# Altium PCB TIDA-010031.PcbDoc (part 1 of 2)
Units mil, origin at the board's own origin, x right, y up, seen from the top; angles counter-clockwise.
Board outline 1982.49 x 1977.57 mil, 2 copper layers (Top Layer, Bottom Layer), stack 62 mil thick; 85 components, 79 nets, 332 pads, 189 vias.
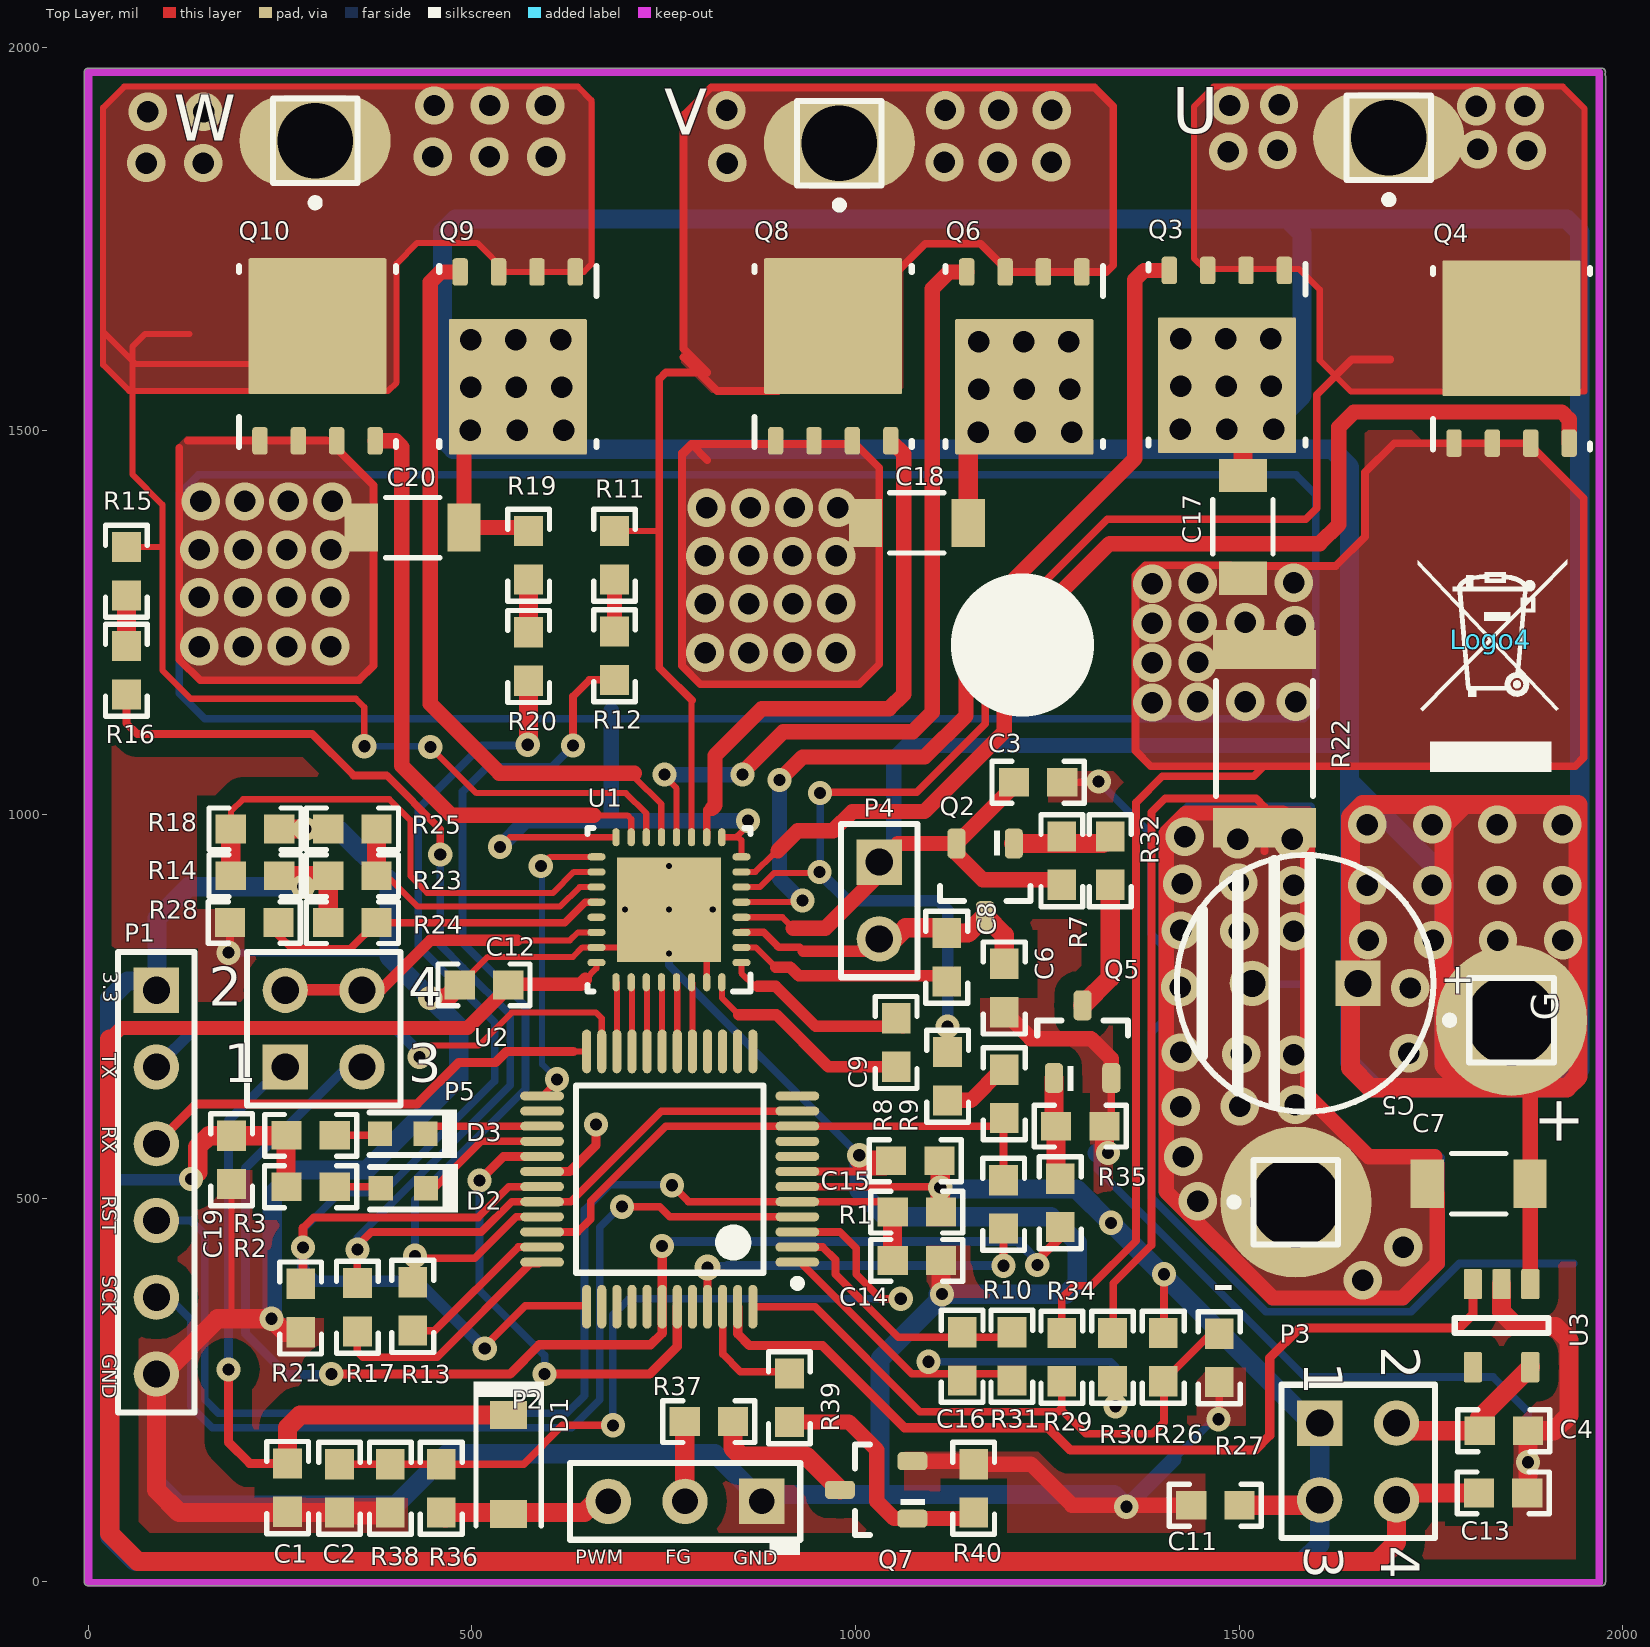
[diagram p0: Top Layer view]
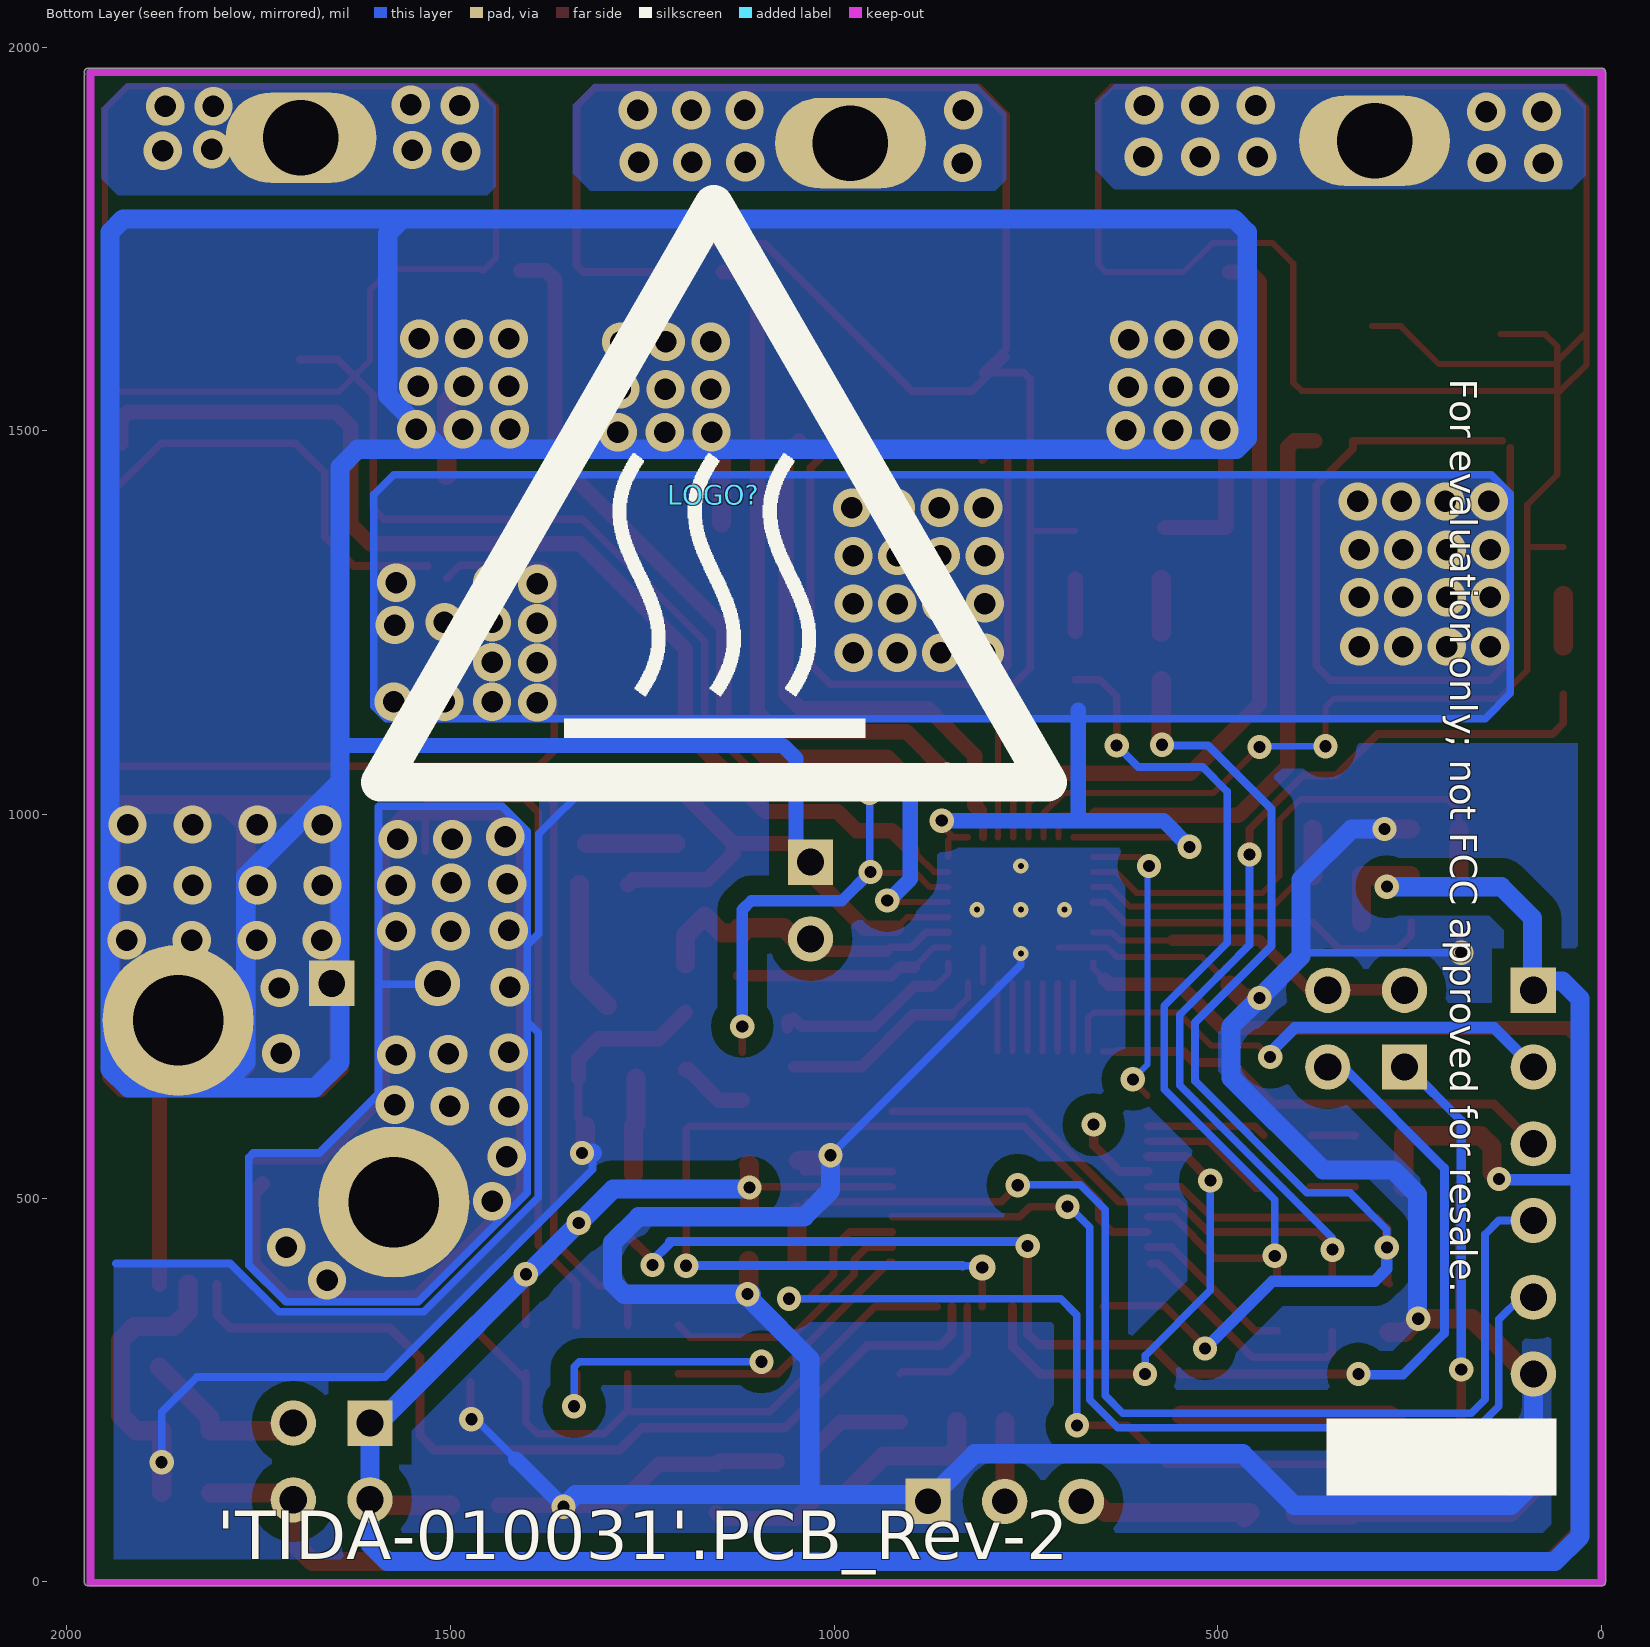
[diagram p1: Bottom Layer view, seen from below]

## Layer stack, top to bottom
Top Solder: solder mask 0.4, Solder Resist, Dk 3.5
Top Layer: signal copper 1.4
Dielectric1: core 59.2, FR-4, Dk 4.8
Bottom Layer: signal copper 1.4
Bottom Solder: solder mask 0.4, Solder Resist, Dk 3.5

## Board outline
0,-5.01 cw(c0,0) -5.01,0 -5.01,1967.54 cw(c0,1967.54) 0,1972.55 1972.46,1972.55 cw(c1972.46,1967.54) 1977.48,1967.54 cw(c1972.46,1967.54) 1976.67,1964.8 cw(c1972.46,1962.07) 1977.48,1962.07 1977.48,0 cw(c1972.46,0) 1972.46,-5.01

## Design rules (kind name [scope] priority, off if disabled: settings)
AcuteAngle [All] p1: minimum=4.50000000000000E+0001 checktracksonly=FALSE
Clearance Clearance_2 [InNet('GND')] p1 off: gap=25 ignorepadtopadclearanceinfootprint=FALSE except(0: Arc-Hole Track-Hole SMDPad-Hole THPad-Hole Via-Hole Fill-Hole Poly-Hole Region-Hole Text-Hole)
Clearance Clearance_Poly [InPolygon] p2 off: gap=10 ignorepadtopadclearanceinfootprint=FALSE except(0: Arc-Hole Track-Hole SMDPad-Hole THPad-Hole Via-Hole Fill-Hole Poly-Hole Region-Hole Text-Hole)
Clearance Clearance_FiducialMark [IsKeepOut and InComponentClass('FiducialMark') vs IsPad and InComponentClass('FiducialMark')] p3 off: gap=30 ignorepadtopadclearanceinfootprint=FALSE except(0: Arc-Hole Track-Hole SMDPad-Hole THPad-Hole Via-Hole Fill-Hole Poly-Hole Region-Hole Text-Hole)
Clearance [All] p4: gap=6 ignorepadtopadclearanceinfootprint=FALSE except(0: Arc-Hole Track-Hole SMDPad-Hole THPad-Hole Via-Hole Fill-Hole Poly-Hole Region-Hole Text-Hole)
ComponentClearance ComponentClearance_MountingHoles_FiducialMarks [InComponentClass('Mounting Holes') vs InComponentClass('FiducialMark')] p1: gap=50 collisioncheckmode=3 verticalgap=10 showdistances=FALSE
ComponentClearance ComponentClearance_Shunt [InComponentClass('Header') vs InComponentClass('Shunt')] p2 off: gap=0 collisioncheckmode=3 verticalgap=0 showdistances=FALSE
ComponentClearance ComponentClearance_Logo [InComponentClass('Logo')] p3 off: gap=50 collisioncheckmode=3 verticalgap=10 showdistances=FALSE
ComponentClearance ComponentClearance_ScrewToNut [(HasFootprint('NY PMS 440 0025 PH')) vs (HasFootprint('Keystone_1902C'))] p4 off: gap=5 collisioncheckmode=3 verticalgap=10 showdistances=FALSE
ComponentClearance ComponentClearance_MountingHoles [InComponentClass('Mounting Holes')] p5 off: gap=250 collisioncheckmode=3 verticalgap=100000 showdistances=FALSE
ComponentClearance ComponentClearance_SmallPassives [HasFootprint('0201*') or HasFootprint('0402*') or HasFootprint('0508') or HasFootprint('0603*') or HasFootprint('0612') or HasFootprint('0805*') or HasFootprint('0815*') or HasFootprint('0830*') or HasFootprint('1206*') or HasFootprint('1210*') or HasFootprint('1808*') or HasFootprint('1812*') or HasFootprint('1825*') or HasFootprint('2010*') or HasFootprint('2220*') or HasFootprint('2225*') or HasFootprint('2512*') or HasFootprint('2728*') or HasFootprint('3518*') vs HasFootprint('0201*') or HasFootprint('0402*') or HasFootprint('0508') or HasFootprint('0603*') or HasFootprint('0612') or HasFootprint('0805*') or HasFootprint('0815*') or HasFootprint('0830*') or HasFootprint('1206*') or HasFootprint('1210*') or HasFootprint('1808*') or HasFootprint('1812*') or HasFootprint('1825*') or HasFootprint('2010*') or HasFootprint('2220*') or HasFootprint('2225*') or HasFootprint('2512*') or HasFootprint('2728*') or HasFootprint('3518*')] p6 off: gap=14.96 collisioncheckmode=3 verticalgap=10 showdistances=FALSE
ComponentClearance ComponentClearance_THtoSMT [IsThruComponent vs IsSMTComponent] p7 off: gap=40 collisioncheckmode=3 verticalgap=30 showdistances=FALSE
ComponentClearance ComponentClearance_THtoTH [IsThruComponent vs IsThruComponent] p8 off: gap=30 collisioncheckmode=3 verticalgap=30 showdistances=FALSE
ComponentClearance [All] p9 off: gap=30 collisioncheckmode=3 verticalgap=10 showdistances=FALSE
DiffPairsRouting [All] p1: maxlimit=100 minlimit=10 mostfreqgap=10 toplayer_minwidth=15 toplayer_maxwidth=15 toplayer_prefwidth=15 bottomlayer_minwidth=15 bottomlayer_maxwidth=15 bottomlayer_prefwidth=15 maxuncoupledlength=1000
FabricationTestPointUsage TestPointUsage [All] p1: valid=2 allowmultiple=FALSE
FabricationTestpoint Testpoint [(IsPad And (OnTopLayer Or OnBottomLayer))] p1: side=3 testpointundercomponent=TRUE minsize=40 maxsize=100 preferedsize=60 minholesize=0 maxholesize=40 preferedholesize=32 testpointgrid=1 allowsidetop=TRUE allowsidebottom=TRUE usegrid=TRUE gridtolerance=0.01
FanoutControl Fanout_LCC [IsLCC] p1: bgadir=Out bgaviamode=Centered fanoutstyle=Auto fanoutdirection=Alternating viagrid=1 // Fanout_LCC (Default Rule)
FanoutControl Fanout_BGA [IsBGA] p2 off: bgadir=Out bgaviamode=Centered fanoutstyle=Auto fanoutdirection=Alternating viagrid=1 // Fanout_BGA (Default Rule)
FanoutControl Fanout_Default [All] p4: bgadir=Out bgaviamode=Centered fanoutstyle=Auto fanoutdirection=Alternating viagrid=1 // Fanout_Default (Default Rule)
FanoutControl Fanout_Small [(CompPinCount < 5)] p5: bgadir=Out bgaviamode=Centered fanoutstyle=Auto fanoutdirection=OutThenIn viagrid=1 // Fanout_Small (Default Rule)
HoleSize [All] p1: absolutevalues=TRUE maxlimit=251 minlimit=7.87 maxpercent=80.000 minpercent=20.000
MinimumAnnularRing MinimumAnnularRing_ThermalPadVias [IsVia and InAnyComponent] p1: minimumring=5.91
MinimumAnnularRing [All] p2 off: minimumring=8
MinimumSolderMaskSliver MinimumSolderMaskSliver_Logo [InComponentClass('Logo') vs InComponentClass('Logo')] p1: minsoldermaskwidth=0.7
MinimumSolderMaskSliver [All] p2 off: minsoldermaskwidth=3.94
PlaneConnect [All] p1: planeconnectstyle=Relief reliefexpansion=10 reliefentries=4 reliefconductorwidth=10 reliefairgap=10
PolygonConnect [All] p1: connectstyle=Direct reliefconductorwidth=10 reliefentries=4 polygonreliefangle="90 Angle" airgapwidth=10
RoutingVias ThermalPadVias [IsVia and InAnyComponent] p1: holewidth=7.87 width=19.68 viastyle="Through Hole" minholewidth=7.87 minwidth=19.68 maxholewidth=12.99 maxwidth=23.62
RoutingVias [All] p2: holewidth=16 width=34 viastyle="Through Hole" minholewidth=7.87 minwidth=26 maxholewidth=40 maxwidth=65
SilkToSilkClearance SilkToSilkClearance_Pb-FreeLogo [(HasFootprint('Pb-Free_Overlay_Medium') OR HasFootprint('Pb-Free_Overlay_Small')) vs (HasFootprint('Pb-Free_Overlay_Medium') OR HasFootprint('Pb-Free_Overlay_Small'))] p1 off: silktosilkclearance=0
SilkToSilkClearance [All] p2 off: silktosilkclearance=4
SilkToSolderMaskClearance SilkToComponentPadClearance [(IsPad or IsFill or IsRegion) and InAnycomponent] p1 off: minsilkscreentomaskgap=5 clearancetoexposedcopper=TRUE
SilkToSolderMaskClearance "Silk to Solder Mask Opening" [IsPad] p2 off: minsilkscreentomaskgap=4 clearancetoexposedcopper=TRUE
SolderMaskExpansion [All] p1: expansion=1.97
Width [All] p1: maxlimit=100 minlimit=6 preferedwidth=10 checkconnectedcopper=TRUE
17 further rules are at their usual default settings.

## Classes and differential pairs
component class TIDA-010031_Page1: + - C1 C2 C3 C4 C5 C6 C7 C8 C9 C11 C12 C13 C14 C15 C16 C17 C18 C19 C20 D1 D2 D3 P1 P2 P3 P4 P5 Q2 Q3 Q4 Q5 Q6 Q7 Q8 Q9 Q10 R1 R2 R3 R7 R8 R9 R10 R11 R12 R13 R14 R15 R16 R17 R18 R19 R20 R21 R22 R23 R24 R25 R26 R27 R28 R29 R30 R31 R32 R34 R35 R36 R37 R38 R39 R40 U U1 U2 U3 V W
component class AssemblyNote: ZZ1 ZZ2
component class Header: P2
component class Label: LBL1
component class TIDA-010031_EVM_Hardware: !PCB LBL1 Logo3 Logo4 ZZ1 ZZ2

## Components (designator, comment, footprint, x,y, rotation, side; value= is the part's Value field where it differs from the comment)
+ "Socket" PIN1#1 1855,732 r90 top (schematic designator J4)
- "Socket" PIN1#1 1574,495 r90 top (schematic designator J5)
C1 "GRM188R61H105KAALD" 0603 260,123 r270 top value=1uF
C2 "C1608X5R1H104K080AA" 0603 327.65,122 r270 top value=0.1uF
C3 "GRM188R61H105KAALD" 0603 1238,1042 r0 top value=1uF
C4 "GRM188R71A225KE15J" 0603 1845,197 r0 top value=2.2uF
C5 "50ZLJ100MT78X11.5" ZLJ_800X1150 1586,780 r180 top value=100uF
C6 "C1608X5R1H104K080AA" 0603 1194,774 r270 top value=0.1uF
C7 "C3216X7R2A474K160AA" 1206_180 1812,519 r180 top value=0.47uF
C8 "GRM188R61H105KAALD" 0603 1119,814 r270 top value=1uF
C9 "C0603X223K5RACTU" 0603 1053,703 r270 top value=0.022uF
C11 "GRM188Z71A106MA73D" 0603 1469,100 r180 top value=10uF
C12 "C1608X5R1H104K080AA" 0603 516,778 r180 top value=0.1uF
C13 "GRM188R61H105KAALD" 0603 1844,116 r0 top value=1uF
C14 "GRM188R71C102KA01D" 0603 1080,419 r0 top value=1000pF
C15 "C1608X5R1H104K080AA" 0603 1078,549 r180 top value=0.1uF
C16 "06035A220JAT2A" 0603 1139,294 r270 top value=22pF
C17 "C3216X7R2A474K160AA" 1206_180 1505,1375 r270 top value=0.47uF
C18 "C3216X7R2A474K160AA" 1206_180 1080,1380 r180 top value=0.47uF
C19 "C1608X5R1H104K080AA" 0603 187,550 r270 top value=0.1uF
C20 "C3216X7R2A474K160AA" 1206_180 423,1374 r180 top value=0.47uF
D1 "1N4148W-TP" SOD-123 548,153 r270 top value=100V
D2 "LTST-C190CKT" LED_LTST-C190_Red 411,513 r0 top value=Red
D3 "LTST-C190CKT" LED_LTST-C190_Red 410,584 r0 top value=Red
Logo3 "FCC disclaimer" FCC_disclaimer 1478,2099 r0 top
Logo4 "WEEE logo" WEEE_Minimum 1828,1228 r0 top
LOGO? "CAUTION HOT SURFACE" IEC_HotSurface_Large 1157,1417.02 r180 bottom
P1 "Header 6" HDR1X6 89,771 r270 top
P2 "800-10-003-10-001000" Mill-Max_800-10-003-10-001000 778,105 r180 top
P3 "Header 2X2" HDR2X2 1605,207 r270 top
P4 "Header 2" HDR1X2 1031,938 r270 top
P5 "Header 2X2" HDR2X2 257,671 r0 top
Q2 "MMBT5401LT1G" SOT-23 1169,915 r270 top value="150 V"
Q3 "CSD18514Q5A" DQJ0008A 1484,1599 r270 top value=40V
Q4 "CSD18514Q5A" DQJ0008A 1855,1594 r90 top value=40V
Q5 "MMBT5550LT1G" SOT-23 1296,704 r90 top value="140 V"
Q6 "CSD18514Q5A" DQJ0008A 1220,1597 r270 top value=40V
Q7 "MMBT5550LT1G" SOT-23 1027,120 r180 top value="140 V"
Q8 "CSD18514Q5A" DQJ0008A 971,1597 r90 top value=40V
Q9 "CSD18514Q5A" DQJ0008A 560,1597 r270 top value=40V
Q10 "CSD18514Q5A" DQJ0008A 299,1597 r90 top value=40V
R1 "RC0603JR-0747KL" 0603 1080,482 r0 top value=47k
R2 "RC0603JR-07470RL" 0603 290,515 r180 top value=470
R3 "RC0603JR-07470RL" 0603 290.04,582 r180 top value=470
R7 "RC0603JR-0751KL" 0603 1269,940 r90 top value=51k
R8 "RC0603FR-0782KL" 0603 1120,659 r270 top value=82.0k
R9 "RC0603FR-0782KL" 0603 1194,636 r270 top value=82.0k
R10 "CRCW060315K0FKEA" 0603 1193,492 r270 top value=15.0k
R11 "RC0603FR-0782KL" 0603 686,1338 r270 top value=82.0k
R12 "RC0603FR-0782KL" 0603 686,1207 r270 top value=82.0k
R13 "CRCW060315K0FKEA" 0603 423,359 r270 top value=15.0k
R14 "RC0603JR-070RL" 0603 217.55,920.3 r0 top value=0
R15 "RC0603FR-0782KL" 0603 50,1317 r270 top value=82.0k
R16 "RC0603FR-0782KL" 0603 50,1188 r270 top value=82.0k
R17 "CRCW060315K0FKEA" 0603 351,358 r270 top value=15.0k
R18 "CRCW060347K0FKEA" 0603 217.55,981.3 r180 top value=47.0k
R19 "CRCW06031M30FKEA" 0603 574,1338 r270 top value=1.30Meg
R20 "CRCW06031M30FKEA" 0603 574,1206 r270 top value=1.30Meg
R21 "CRCW0603150KFKEA" 0603 277,357 r270 top value=150k
R22 "ERJ-M1WTF1M0U" 2512 1533,1099 r90 top value=0.001
R23 "RC0603JR-070RL" 0603 344.55,920.3 r180 top value=0
R24 "RC0603JR-070RL" 0603 344.55,859.3 r180 top value=0
R25 "CRCW060375K0JNEA" 0603 344.55,981.3 r0 top value=75k
R26 "CRCW06037K50FKEA" 0603 1401,293 r270 top value=7.50k
R27 "CRCW06037K50FKEA" 0603 1474,292 r270 top value=7.50k
R28 "CRCW06031M00FKEA" 0603 216.55,859.3 r0 top value=1.00Meg
R29 "ERJ-3EKF1001V" 0603 1269,293 r270 top value=1.00k
R30 "ERJ-3EKF1001V" 0603 1335,293 r270 top value=1.00k
R31 "RC0603FR-0720KL" 0603 1204,294 r90 top value=20.0k
R32 "ERJ-3GEYJ104V" 0603 1332,940 r90 top value=100k
R34 "RC0603JR-0751KL" 0603 1267,494 r90 top value=51k
R35 "ERJ-3GEYJ104V" 0603 1293,594 r180 top value=100k
R36 "CRCW060351K0JNEA" 0603 460.21,122 r90 top value=51k
R37 "CRCW0603100RJNEA" 0603 809,209 r0 top value=100
R38 "ERJ-3GEYJ104V" 0603 393.96,122 r90 top value=100k
R39 "RC0603JR-0751KL" 0603 914,240 r90 top value=51k
R40 "ERJ-3GEYJ104V" 0603 1154,122 r270 top value=100k
U "Socket" PIN1#2 1695,1882 r180 top (schematic designator J1)
U1 "DRV8320HRTVR" RTV0032E 757,876 r180 top
U2 "MSP430FR2355TPT" PT0048A_N 758,525 r180 top
U3 "TPS70933DBVR" DBV0005A_N 1842,334 r270 top
V "Socket" PIN1#2 979,1875 r180 top (schematic designator J2)
W "Socket" PIN1#2 296,1878 r180 top (schematic designator J3)
ZZ1 "This Assembly Note is for PCB labels only" AssemblyNoteLabel -798.54,3189 r0 top
ZZ2 "These assemblies are ESD sensitive, ESD precautions shall be observed." AssemblyNote -798.54,3080.11 r0 top

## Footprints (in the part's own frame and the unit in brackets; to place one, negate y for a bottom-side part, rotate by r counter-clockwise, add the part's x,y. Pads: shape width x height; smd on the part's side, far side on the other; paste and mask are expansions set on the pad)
0603 [mm] "0603 from SM-752 data"
  rect 1x0.95 smd: 1(-0.8,0) 2(0.8,0)
  silkscreen extent -1.52,-0.69 1.52,0.69, body extent -0.87,-0.47 0.87,0.47, height 1
1206_180 [mm] "1206_180"
  rect 1.1x1.6 smd: 1(-1.7,0) 2(1.7,0)
  silkscreen extent -0.9,-1 0.9,1, body extent -1.75,-0.95 1.75,0.95, height 1.8
2512 [mm] "Chip Resistor, Body 6.3x3.2mm, IPC Medium Density"
  rect 1.3x3.4 smd: 1(-2.95,0) 2(2.95,0)
  silkscreen extent -1.9,-1.6 1.9,1.6, body extent -3.22,-1.67 3.22,1.67, height 0.71
AssemblyNote [mil] "Assembly Note"
AssemblyNoteLabel [mil] "Assembly Note for PCB Labels"
DBV0005A_N [mm] "SOT23, 5-Leads, Body 2.9x1.6mm, Pitch 0.95mm, Lead Span 2.8mm, IPC Medium Density"
  rrect17% 1x0.6 smd: 1(-1.375,0.95) 2(-1.375,0) 3(-1.375,-0.95) 4(1.375,-0.95) 5(1.375,0.95)
  silkscreen extent -0.25,-1.55 0.25,1.55, body extent -1.42,-1.46 1.42,1.46, height 1.09
DQJ0008A [mm] "SMD, 8-Leads, Body 5.75x4.9mm"
  rrect39% 0.91x0.51 smd paste-0.05 mask-0.05: 1(-2.795,1.905) 2(-2.795,0.635) 3(-2.795,-0.635) 4(-2.795,-1.905) 5(2.795,-1.905) 6(2.795,-0.635) 7(2.795,0.635) 8(2.795,1.905)
  rrect8% 1.58x1.25 on Top Paste: 9(-0.38,1.45) 9(-0.38,0) 9(-0.38,-1.45) 9(1.4,1.45) 9(1.4,0) 9(1.4,-1.45)
  rrect3% 3.48x4.47 on Top Solder: 9(0.55,0)
  rrect2% 4.49x4.57 smd paste-2.5 mask-2.5: 9(1.005,0)
  silkscreen extent -3,-2.6 3,2.6, body extent -3.13,-2.45 3.13,2.45, height 1.15
FCC_disclaimer [mil]
HDR1X2 [mm] "Connector; Header; 2 Position"
  rect 1.5x1.5 hole 0.9: 1(0,0)
  round 1.5 hole 0.9: 2(2.54,0)
  silkscreen extent -1.27,-1.27 3.81,1.27
HDR1X6 [mm] "Connector; Header; 6 Position"
  rect 1.5x1.5 hole 0.9: 1(0,0)
  round 1.5 hole 0.9: 2(2.54,0) 3(5.08,0) 4(7.62,0) 5(10.16,0) 6(12.7,0)
  silkscreen extent -1.27,-1.27 13.97,1.27
HDR2X2 [mm] "Connector; Header; 2x2 Position"
  rect 1.5x1.5 hole 0.9: 1(0,0)
  round 1.5 hole 0.9: 2(0,2.54) 3(2.54,0) 4(2.54,2.54)
  silkscreen extent -1.27,-1.27 3.81,3.81
IEC_HotSurface_Large [mil]
  silkscreen extent -435,-375 435,378
LED_LTST-C190_Red [mm] "Lite-On"
  rect 0.8x0.8 smd: 1(-0.75,0) 2(0.75,0)
  silkscreen extent -1.1,-0.8 1.8,0.8, body extent -0.85,-0.45 0.85,0.45, height 0.9
Mill-Max_800-10-003-10-001000 [mm] "Mill-Max"
  rect 1.5x1.5 hole 0.85: 1(-2.54,0)
  round 1.5 hole 0.85: 2(0,0) 3(2.54,0)
  silkscreen extent -3.81,-1.27 3.81,1.78, body extent -3.81,-1.27 3.81,1.27, height 8.13
PIN1#1 [mm] "Connector; Plug"
  round 5 hole 3: 1(0,0)
  silkscreen extent -1.4,-1.4 1.4,2.17
PIN1#2 [mm] "Connector; Plug"
  oval 5x3 hole 2.5: 1(0,0)
  silkscreen extent -1.4,-1.4 1.4,2.17
PT0048A_N [mm] "Thin QFP, 48-Leads, Body 7x7mm, Pitch 0.5mm, IPC Medium Density"
  oval 1.45x0.3 smd: 1(-4.225,2.75) 2(-4.225,2.25) 3(-4.225,1.75) 4(-4.225,1.25) 5(-4.225,0.75) 6(-4.225,0.25) 7(-4.225,-0.25) 8(-4.225,-0.75) 9(-4.225,-1.25) 10(-4.225,-1.75) 11(-4.225,-2.25) 12(-4.225,-2.75) 25(4.225,-2.75) 26(4.225,-2.25) 27(4.225,-1.75) 28(4.225,-1.25) 29(4.225,-0.75) 30(4.225,-0.25) 31(4.225,0.25) 32(4.225,0.75) 33(4.225,1.25) 34(4.225,1.75) 35(4.225,2.25) 36(4.225,2.75)
  oval 0.3x1.45 smd: 13(-2.75,-4.225) 14(-2.25,-4.225) 15(-1.75,-4.225) 16(-1.25,-4.225) 17(-0.75,-4.225) 18(-0.25,-4.225) 19(0.25,-4.225) 20(0.75,-4.225) 21(1.25,-4.225) 22(1.75,-4.225) 23(2.25,-4.225) 24(2.75,-4.225) 37(2.75,4.225) 38(2.25,4.225) 39(1.75,4.225) 40(1.25,4.225) 41(0.75,4.225) 42(0.25,4.225) 43(-0.25,4.225) 44(-0.75,4.225) 45(-1.25,4.225) 46(-1.75,4.225) 47(-2.25,4.225) 48(-2.75,4.225)
  silkscreen extent -4.35,-3.1 3.1,3.57, body extent -4.51,-4.51 4.51,4.51, height 1.5
RTV0032E [mm] "QFN, 32-Leads, Body 5x5mm, Pitch 0.5mm"
  oval 0.6x0.24 smd: 1(-2.4,1.75) 2(-2.4,1.25) 3(-2.4,0.75) 4(-2.4,0.25) 5(-2.4,-0.25) 6(-2.4,-0.75) 7(-2.4,-1.25) 8(-2.4,-1.75) 17(2.4,-1.75) 18(2.4,-1.25) 19(2.4,-0.75) 20(2.4,-0.25) 21(2.4,0.25) 22(2.4,0.75) 23(2.4,1.25) 24(2.4,1.75)
  oval 0.24x0.6 smd: 9(-1.75,-2.4) 10(-1.25,-2.4) 11(-0.75,-2.4) 12(-0.25,-2.4) 13(0.25,-2.4) 14(0.75,-2.4) 15(1.25,-2.4) 16(1.75,-2.4) 25(1.75,2.4) 26(1.25,2.4) 27(0.75,2.4) 28(0.25,2.4) 29(-0.25,2.4) 30(-0.75,2.4) 31(-1.25,2.4) 32(-1.75,2.4)
  rect 3.45x3.45 smd paste-1.8: 33(0,0)
  silkscreen extent -2.7,-2.7 2.7,2.7, body extent -2.55,-2.55 2.55,2.55, height 0.81
SOD-123 [mm] "On Semi recommended land pattern"
  rect 0.915x1.22 smd: 1(-1.637,0) 2(1.637,0)
  silkscreen extent -2.74,-1.17 2.03,1.17, body extent -1.93,-0.9 1.93,0.9, height 1.35
SOT-23 [mm] "SOT23, 3-Leads, Body 2.9x1.3mm, Pitch 0.95mm, Lead Span 2.5mm, IPC Medium Density"
  rrect50% 1x0.6 smd: 1(-1.2,0.95) 2(-1.2,-0.95) 3(1.2,0)
  silkscreen extent -1.63,-1.5 0.7,1.5, body extent -1.16,-1.45 1.21,1.45, height 1
WEEE_Minimum [mil] "WEEElie bin"
  silkscreen extent -95,-172 99,104
ZLJ_800X1150 [mm] "Rubycon"
  rect 1.5x1.5 hole 0.889: 1(-1.75,0)
  round 1.5 hole 0.889: 2(1.75,0)
  silkscreen extent -4.25,-4.25 4.25,4.25, body extent -4.22,-4.24 4.24,4.24, height 13.01

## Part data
C1 C3 C8 C13: library part CMP-0007350-5, "CAP, CERM, 1 uF, 50 V, +/- 10%, X5R, 0603", Cap_Case=0603, Manufacturer=MuRata, Supplier Part Number 1=13T1194, TempCo=X5R, Tolerance_%=10%, Value1=Unknown, Value2=50V, ValueDisplayed=1uF
C2: library part CMP-0007010-5, "CAP, CERM, 0.1 uF, 50 V, +/- 10%, X5R, 0603", Cap_Case=0603, Manufacturer=TDK, Supplier Part Number 1=445-7456-1-ND, TempCo=X5R, Tolerance_%=10%, Value1="0.0296 ohm", Value2=50V, ValueDisplayed=1uF
C4: library part CMP-0084284-1, "CAP, CERM, 2.2 µF, 10 V,+/- 10%, X7R, AEC-Q200 Grade 1, 0603", Cap_Case=0603, Manufacturer=MuRata, TempCo=X7R, Tolerance_%=10%, Value2=10V, ValueDisplayed=2.2µF
C5: library part CMP-0009787-2, "CAP, AL, 100 uF, 50 V, +/- 20%, 0.12 ohm, TH", Cap_Case=8x11.5, Manufacturer=Rubycon, Supplier Part Number 1=1189-1662-1-ND, Tolerance_%=20%, Value1="0.12 ohm", Value2=50V, ValueDisplayed=100uF
C6 C12 C15 C19: library part CMP-0007010-5, "CAP, CERM, 0.1 uF, 50 V, +/- 10%, X5R, 0603", Cap_Case=0603, Manufacturer=TDK, Supplier Part Number 1=445-7456-1-ND, TempCo=X5R, Tolerance_%=10%, Value1="0.0296 ohm", Value2=50V, ValueDisplayed=0.1uF
C7 C17 C18 C20: library part CMP-0008716-2, "CAP, CERM, 0.47 uF, 100 V, +/- 10%, X7R, 1206", Cap_Case=1206_180, Manufacturer=TDK, Supplier Part Number 1=445-2284-1-ND, TempCo=X7R, Tolerance_%=10%, Value1="0.007558 ohm", Value2=100V, ValueDisplayed=0.47uF
C9: library part CMP-0006984-4, "CAP, CERM, 0.022 uF, 50 V, +/- 10%, X7R, 0603", Cap_Case=0603, Manufacturer=Kemet, Supplier Part Number 1=399-5340-1-ND, TempCo=X7R, Tolerance_%=10%, Value1=Unknown, Value2=50V, ValueDisplayed=0.022uF
C11: library part CMP-0007497-5, "CAP, CERM, 10 uF, 10 V, +/- 20%, X7R, 0603", Cap_Case=0603, Manufacturer=MuRata, Supplier Part Number 1=81-GRM188Z71A106MA3D, TempCo=X7R, Tolerance_%=20%, Value1=Unknown, Value2=10V, ValueDisplayed=10uF
C14: library part CMP-0007376-4, "CAP, CERM, 1000 pF, 16 V, +/- 10%, X7R, 0603", Cap_Case=0603, Manufacturer=MuRata, Supplier Part Number 1=GRM188R71C102KA01D-ND, TempCo=X7R, Tolerance_%=10%, Value1=Unknown, Value2=16V, ValueDisplayed=1000pF
C16: library part CMP-0006775-4, "CAP, CERM, 22 pF, 50 V, +/- 5%, C0G/NP0, 0603", Cap_Case=0603, Manufacturer=AVX, Supplier Part Number 1=478-1167-1-ND, TempCo=C0G/NP0, Tolerance_%=5%, Value1="0.259 ohm", Value2=50V, ValueDisplayed=22pF
D1: library part CMP-0076974-1, "Diode, Switching, 100 V, 0.15 A, SOD-123", Manufacturer="Micro Commercial Components", Supplier Part Number 1=1N4148WTPMSCT-ND, Value1=0.15A, Value2=1.25V
D2 D3: library part CMP-0002842-1, "LED, Red, SMD", Color=red, Manufacturer=Lite-On, Power_TotalModule=62.5mW, Supplier Part Number 1=160-1181-1-ND, Value1=0.0625W, Value2=2V
Logo3: library part CMP-0074847-1, "FCC_disclaimer"
Logo4: library part CMP-0074769-1
LOGO?: library part CMP-0074837-1, "IEC 61010-1 Hot Surface Warning"
P1: library part CMP-0055084-1, "Header, 100mil, 6x1, TH"
P2: library part CMP-0055086-1, "Header, 100mil, 3x1, TH", Manufacturer=Mill-Max, Supplier Part Number 1=ED7203-ND
P3 P5: library part CMP-0054558-1, "Header, 100mil, 2x2, Tin, TH"
P4: library part CMP-0055085-1, "Header, 100mil, 2x1, TH"
Q2: library part CMP-0000333-2, "Transistor, PNP, 150 V, 0.5 A, SOT-23", Manufacturer="ON Semiconductor", Supplier Part Number 1=MMBT5401LT1GOSCT-ND, Value1="0.5 A", Value2=240
Q3 Q4 Q6 Q8 Q9 Q10: library part CMP-0000715-1, "MOSFET, N-CH, 40 V, 50 A, DQJ0008A (VSONP-8)", Alternate Manufacturer=None, Manufacturer="Texas Instruments", Supplier Part Number 1=CSD18514Q5A-ND, Value1=0.007, Value2="29 nC"
Q5 Q7: library part CMP-0000411-2, "Transistor, NPN, 140 V, 0.6 A, SOT-23", Manufacturer="ON Semiconductor", Supplier Part Number 1=MMBT5550LT1GOSCT-ND, Value1="0.6 A", Value2=250
R1: library part CMP-0025925-5, "RES, 47 k, 5%, 0.1 W, 0603", Manufacturer=Yageo, Power_W=100mW, Supplier Part Number 1=311-47KGRCT-ND, TempCo="100 ppm/C", Tolerance_%=5%, Value2=0.1W, Value_Code=47k0, ValueDisplayed=47k
R2 R3: library part CMP-0025924-5, "RES, 470, 5%, 0.1 W, 0603", Manufacturer=Yageo, Power_W=100mW, Supplier Part Number 1=311-470GRCT-ND, TempCo="100 ppm/C", Tolerance_%=5%, Value2=0.1W, Value_Code=470R, ValueDisplayed=470
R7 R34 R39: library part CMP-0025929-5, "RES, 51 k, 5%, 0.1 W, 0603", Manufacturer=Yageo, Power_W=100mW, Supplier Part Number 1=311-51KGRCT-ND, TempCo="100 ppm/C", Tolerance_%=5%, Value2=0.1W, Value_Code=51k0, ValueDisplayed=51k
R8 R9 R11 R12 R15 R16: library part CMP-0023292-5, "RES, 82.0 k, 1%, 0.1 W, 0603", Manufacturer=Yageo, Power_W=100mW, Supplier Part Number 1=311-82.0KHRCT-ND, TempCo="100 ppm/C", Tolerance_%=1%, Value2=0.1W, Value_Code=82k0, ValueDisplayed=82.0k
R10 R13 R17: library part CMP-0022066-4, "RES, 15.0 k, 1%, 0.1 W, AEC-Q200 Grade 0, 0603", Manufacturer=Vishay-Dale, Power_W=100mW, Supplier Part Number 1=541-15.0KHCT-ND, TempCo="100 ppm/C", Tolerance_%=1%, Value2=0.1W, Value_Code=15k0, ValueDisplayed=10.0k
R14 R23 R24: library part CMP-0025885-5, "RES, 0, 5%, 0.1 W, 0603", Manufacturer=Yageo, Power_W=100mW, Supplier Part Number 1=311-0.0GRCT-ND, TempCo="200 ppm/C", Tolerance_%=5%, Value2=0.1W, Value_Code=0000, ValueDisplayed=0
R18: library part CMP-0022438-4, "RES, 47.0 k, 1%, 0.1 W, AEC-Q200 Grade 0, 0603", Manufacturer=Vishay-Dale, Power_W=100mW, Supplier Part Number 1=541-47.0KHCT-ND, TempCo="100 ppm/C", Tolerance_%=1%, Value2=0.1W, Value_Code=47k0, ValueDisplayed=47.0k
R19 R20: library part CMP-0022150-4, "RES, 1.30 M, 1%, 0.1 W, AEC-Q200 Grade 0, 0603", Manufacturer=Vishay-Dale, Power_W=100mW, Supplier Part Number 1=541-1.30MHCT-ND, TempCo="100 ppm/C", Tolerance_%=1%, Value2=0.1W, Value_Code=1M30, ValueDisplayed=1.30M
R21: library part CMP-0022060-4, "RES, 150 k, 1%, 0.1 W, AEC-Q200 Grade 0, 0603", Manufacturer=Vishay-Dale, Power_W=100mW, Supplier Part Number 1=541-150KHCT-ND, TempCo="100 ppm/C", Tolerance_%=1%, Value2=0.1W, Value_Code=150k
R22: library part CMP-0015817-2, "RES, 0.001, 1%, 1 W, 2512", Manufacturer=Panasonic, Power_W=1W, Supplier Part Number 1=P1.0NDCT-ND, TempCo=ppm/C, Tolerance_%=1%, Value_Code=1L000, ValueDisplayed=0.001
R25: library part CMP-0025853-4, "RES, 75 k, 5%, 0.1 W, AEC-Q200 Grade 0, 0603", Manufacturer=Vishay-Dale, Power_W=100mW, Supplier Part Number 1=541-75KGCT-ND, TempCo="200 ppm/C", Tolerance_%=5%, Value2=0.1W, Value_Code=75k0, ValueDisplayed=75k
R26 R27: library part CMP-0022601-4, "RES, 7.50 k, 1%, 0.1 W, AEC-Q200 Grade 0, 0603", Manufacturer=Vishay-Dale, Power_W=100mW, Supplier Part Number 1=541-7.50KHCT-ND, TempCo="100 ppm/C", Tolerance_%=1%, Value2=0.1W, Value_Code=7k50, ValueDisplayed=7.50k
R28: library part CMP-0022138-4, "RES, 1.00 M, 1%, 0.1 W, AEC-Q200 Grade 0, 0603", Manufacturer=Vishay-Dale, Power_W=100mW, Supplier Part Number 1=541-1.00MHCT-ND, TempCo="100 ppm/C", Tolerance_%=1%, Value2=0.1W, Value_Code=1M00, ValueDisplayed=1.00M
R29 R30: library part CMP-0022680-4, "RES, 1.00 k, 1%, 0.1 W, 0603", Manufacturer=Panasonic, Power_W=100mW, Supplier Part Number 1=P1.00KHCT-ND, TempCo="100 ppm/C", Tolerance_%=1%, Value2=0.1W, Value_Code=1k00, ValueDisplayed=1.00k
R31: library part CMP-0022906-5, "RES, 20.0 k, 1%, 0.1 W, 0603", Manufacturer=Yageo, Power_W=100mW, Supplier Part Number 1=311-20.0KHRCT-ND, TempCo="100 ppm/C", Tolerance_%=1%, Value2=0.1W, Value_Code=20k0, ValueDisplayed=3.9k
R32 R35 R38 R40: library part CMP-0025875-3, "RES, 100 k, 5%, 0.1 W, AEC-Q200 Grade 0, 0603", Manufacturer=Panasonic, Power_W=100mW, Supplier Part Number 1=P100KGCT-ND, TempCo="200 ppm/C", Tolerance_%=5%, Value2=0.1W, Value_Code=100k
R36: library part CMP-0025824-4, "RES, 51 k, 5%, 0.1 W, AEC-Q200 Grade 0, 0603", Manufacturer=Vishay-Dale, Power_W=100mW, Supplier Part Number 1=541-51KGCT-ND, TempCo="200 ppm/C", Tolerance_%=5%, Value2=0.1W, Value_Code=51k0, ValueDisplayed=51k
R37: library part CMP-0025700-4, "RES, 100, 5%, 0.1 W, AEC-Q200 Grade 0, 0603", Manufacturer=Vishay-Dale, Power_W=100mW, Supplier Part Number 1=541-100GCT-ND, TempCo="200 ppm/C", Tolerance_%=5%, Value2=0.1W, Value_Code=100R, ValueDisplayed=100
U1: library part CMP-0078607-1, "60V Three-Phase Smart Gate Driver, RTV0032E (WQFN-32)", Alternate Manufacturer="Texas Instruments", Alternate PartNumber=DRV8320HRTVT
U2: library part CMP-0013603-2, "Mixed-Signal Microcontroller, PT0048A (LQFP-48)", Alternate Manufacturer="Texas Instruments"
U3: library part CMP-0073793-1, "150-mA, 30-V, Ultra-Low IQ, Wide Input Low-Dropout Regulator with Reverse Current Protection, DBV0005A (SOT-23-5)", Alternate Manufacturer="Texas Instruments", Alternate PartNumber=TPS70933DBVT
ZZ1: library part CMP-0003616-3
ZZ2: library part CMP-0077236-1

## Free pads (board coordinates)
  round 30 smd far side: 1(662,596)

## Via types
v1: diameter 50, hole 28, Top Layer to Bottom Layer, 132 vias
v2: diameter 31.5, hole 15.75, Top Layer to Bottom Layer, 51 vias
v3: diameter 19.68, hole 7.87, Top Layer to Bottom Layer, 5 vias
v4: diameter 34, hole 16, Top Layer to Bottom Layer, 1 vias

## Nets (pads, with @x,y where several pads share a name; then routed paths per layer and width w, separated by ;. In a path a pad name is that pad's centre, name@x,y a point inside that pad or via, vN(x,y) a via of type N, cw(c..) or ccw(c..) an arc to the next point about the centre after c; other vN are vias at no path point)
3V3: C11.1 C15.1 C19.1 P1.1 P3.1 P3.3 R1.2 R2.2 R3.2 R14.2 R23.2 R24.2 R26.1 U2.6 | length 4367.5
  Top Layer w10: C19.1@185.54,573.5 C19.1@194.04,582 ; R3.2@258.54,582 R3.2@261.04,579.5 ; U2.6@924.34,515.16 v2@1108.7,515.16 ; R26.1@1402,335.5 v2(1402,401)
  Top Layer w25: v2(134,525) 143,534 143,567 157.5,581.5 C19.1@187,581.5 258.04,581.5 258.04,515.46 R2.2@258.5,515 ; R14.2@249.05,920.3 v2@280,920.3 ; v2(280,906) v2@280,920.3 ; R24.2@313.06,859.3 R23.2@313.06,920.3 v2@280,920.3 ; R1.2@1110.5,480 v2(1110.5,514) 1110.5,543 C15.1@1111.5,544 ; C11.1@1500.5,100 1598,100 P3.3@1605,107
  Bottom Layer w15: 28.22,524 133,524 v2(134,525)
  Bottom Layer w25: v2(280,906) 131,906 90,865 90,783 51.22,783 28.22,760 28.22,524 28.22,59.31 61,26.53 496,26.53 ; 518,26.53 496,26.53 ; v2(1110.5,514) 1112.5,512 1288,512 1332,468 v2(1333,468) P3.1@1594,207 ; P3.1@1605,207 1605,49 1582.53,26.53 496,26.53
BCL_RXD: P1.3 U2.24 | length 610.6
  Top Layer w8: 632.34,691.34 U2.24@649.73,691.34
  Top Layer w12: P1.3@89,571 141,623 429,623 483,677 531,677 545.34,691.34 632.34,691.34
BCL_TXD: P1.2 U2.23 | length 691.1
  Top Layer w8: v2(432,684) 447,699 509,699 552,742 632,742 662,742 669.42,734.58 U2.23@669.42,691.34
  Bottom Layer w15: P1.2@89,671 140,722 400,722 432,690 v2(432,684)
BEMF_C: R20.2 R21.1 U2.31 U2.37 | length 1889.9
  Top Layer w10: R21.1@277,388.5 R21.1@280,391.5 ; 280,461 294,475 508.34,475 548.5,515.16 U2.31@591.66,515.16 ; v2(517,304) 517,307 570,360 648.39,360 U2.37@649.73,358.66 ; v2(573,1091) 573,1090 v2@574,1091
  Top Layer w12: R21.1@280,391.5 v2(280,436) 280,461
  Top Layer w25: v2(573,1091) 574,1092 R20.2@574,1174.5
  Bottom Layer w10: v2(280,436) 280,459 328,507 384.09,507 530,652.91 530,729 430.25,828.75 430.25,1007.25 513,1090 572,1090 v2(573,1091) ; v2(517,304) v2@517,307
  Bottom Layer w15: v2(280,436) 280,408 296,392 429,392 v2(517,304)
COMP0_O: pad.1 U2.30 | length 111.5
  Top Layer w12: U2.30@591.66,534.84 627.84,534.84 662,569 v2(662,596)
COMP1_O: U2.29 U2.43 | length 621.7
  Top Layer w8: U2.29@591.44,554.75 U2.29@591.66,554.53
  Top Layer w12: v2(510,523) 541.53,554.53 U2.29@591.66,554.53 ; v2(595,271) 732,271 767.84,306.84 U2.43@767.84,358.66
  Bottom Layer w10: v2(510,523) 510,380 595,295 v2(595,271)
DVDD: C12.1 C13.1 P3.4 U1.24 | length 3180.3
  Top Layer w8: 648,785 662.51,799.51 U1.24@662.51,807.1
  Top Layer w18: 28.22,707.22 43,722 494.46,722 C12.1@548.46,776 ; C12.1@547.5,779 642,779 648,785
  Top Layer w25: 28.22,707.22 28.22,63 64.69,26.53 1680,26.53 1705,51.53 P3.4@1705,107 ; P3.4@1714,116 C13.1@1812.5,116
EMG: U1.17 U2.25 | length 400.9
  Top Layer w8: v2(590,933) 601.9,944.9 U1.17@662.51,944.9 ; U2.25@591.66,633.27 611,652.61 v2(611,655)
  Bottom Layer w8: v2(590,933) 591.66,931.34 591.66,675 ; 591.66,682 591.66,674.34 v2(611,655)
Enable: P5.2 P5.4 U1.22 | length 436.4
  Top Layer w8: 559,836 628,836 638.47,846.47 U1.22@662.51,846.47
  Top Layer w15: P5.2@257,772 382,772 446,836 559,836
FG: R39.2 U2.46 | length 159.3
  Top Layer w10: U2.46@826.9,358.66 826.9,297.1 850,274 911.5,274 R39.2@914,271.5
GND: -.1 C1.2 C2.2 C3.2 C4.2 C5.2 C6.2 C7.2 C11.2 C12.2 C13.2 C14.2 C15.2 C19.2 P1.6 P2.1 Q5.2 Q7.2 R18.1 R21.2 R22.1 R25.1 R27.2 R28.1 R30.1 R35.1 R38.1 R40.1 U1.23 U1.31 U1.33 U2.7 U3.2 | length 13552.6
  Top Layer w8: 187,338 C19.2@187,518.5 ; C12.2@484.5,778 521,814.5 540.5,814.5 631.96,814.5 644.24,826.79 U1.23@662.51,826.79 U1.33@707.79,826.79 ; U1.31@806.21,781.51 U1.33@806.21,826.79
  Top Layer w10: v2(183,820) 185.06,822.05 R28.1@185.06,859.3 ; U2.7@924.34,534.84 1005,534.84 ; v2(1005,556) 1005,534.84 ; C15.2@1039.66,534.84 1005,534.84 ; C3.2@1269.5,1042 1316,1042 v2(1317,1043) ; R35.1@1333.4,602.91 Q5.2@1333.4,656.76 ; R30.1@1336,334.5 1336,389 1385.7,438.7 1385.7,1003 1403.7,1021 1522,1021 1533,1010 R22.1@1533,982.86 1533,952 ; v2(1473,212) 1474,213 R27.2@1474,260.5
  Top Layer w20: Q7.2@1074.24,157.4 1150.09,157.4 R40.1@1154,153.5 1228.5,153.5 1282,100 v2@1355,100 ; C6.2@1194,742.5 1228.5,708 1307,708 1333.4,681.6 Q5.2@1333.4,656.76 ; v2(1353,98) v2@1355,100 ; C11.2@1437.5,100 v2@1355,100 ; R22.1@1470,1002 1542,1002 R22.1@1557,1002 ; v1@1589,635 1589,876 ; C7.2@1745.07,519 1758,506.07 1758,415 1713,370 1544,370 1405,509 1405,976 1431,1002 R22.1@1557,1002 ; 1755,554 1669,554 1589,634 1589,970 R22.1@1557,1002
  Top Layer w25: R18.1@249.05,981.3 v2(283,981.3) R25.1@313.06,981.3 ; R21.2@277,325.5 256.5,325.5 v2(239,343) 169,343 97,271 P1.6@89,271 89,120 118.5,90.5 C2.2@327.65,90.5 ; v2(446,761) 467.5,761 C12.2@484.5,778 ; v2@1005,550 1045.5,550 C15.2@1046.5,549 ; C14.2@1111.5,419 1111.5,376.5 v2(1113,375) ; R35.1@1324.5,594 1324.5,563.5 v2(1329,559) ; U3.2@1842,388.13 1842,352 1861,333 1912,333 1930,315 1930,217 1910,197 C4.2@1876.5,197 v2(1876.5,156) C13.2@1876.5,117
  Top Layer w30: C2.2@326.46,90 362.46,90 R38.1@396.96,90
  Bottom Layer w10: v2(183,820) 387,820 392,815 ; v3(757,818.91) 757,804 v2(1005,556) ; v2@1315.02,559 1315.02,537.98 1586,267 1627,267 ; v2(1317,1043) 1385,975 1385,845 1400,830 ; 1415,160 1467,212 v2(1473,212) ; C5.2@1517.1,780 1518.1,779 1591,779 1594,782 1594,1010 1593,1011 1433,1011 1400,978 1400,730 ; 1594,824 1594,636 1671,559 1757,559 1763,553 1763,413 1715,365 1542,365 1400,507 1400,730 ; 1633,267 1627,267 ; v2(1876.5,156) 1876.5,221.5 1831,267 1627,267 ; 1936,415 1787,415 1724,352 1535,352 1385.7,501.3 1385.7,715.7 1400,730
  Bottom Layer w20: v2(1353,98) 1415,160
  Bottom Layer w25: P1.6@89,271 89,129 118,100 400.67,100 467.67,167 817,167 870,114 1337,114 v2(1353,98) ; v2(239,343) 240,344 240,505 272,537 363,537 483,657 483,724 v2(446,761) 392,815 392,915 325.7,981.3 v2(283,981.3) ; v2(1005,556) 1005,510 1039,476 1255,476 1289,442 1289,390 1274,375 1108,375 1108,366.74 1031.88,290.62 1031.88,116.88 ; v2@1315.02,559 v2(1329,559)
  other v1: 1661,393 1714,436 1446,496 1427,554 1424,619 1501,620 1573,622 1571,687 1503,688 1424,690 1423,775 1500,848 1571,848 1424,849 1571,908 1426,910 1499,911 1498,968 1569,968 1429,971
  other v3: 699.91,876 757,876 814.09,876 757,933.09
IS: C17.2 C18.2 C20.2 Q4.1 Q4.2 Q4.3 Q8.1 Q8.2 Q8.3 Q10.1 Q10.2 Q10.3 R22.2 R29.1 U1.8 U1.9 U1.16 | length 9245.6
  Top Layer w8: v2(537,958) 549.49,970.49 624.49,970.49 U1.16@688.1,970.49 ; U1.9@825.9,970.49 844.49,970.49 846,972 ; U1.8@851.49,944.9 851.49,966.51 846,972 ; v2(860,992) 860,986 846,972
  Top Layer w10: 119,1477.91 119,1202 146,1175 353,1175 372,1194 372,1429 324,1477 Q10.3@324,1486.96 129.96,1486.96 ; 777,1471 789,1483 999.96,1483 1031,1451.96 1031,1196 1005,1170 798,1170 774,1194 774,1471.09 785.91,1483 807,1461.91 ; R29.1@1269,334.5 1269,370 1285,386 1307,386 1365.7,444.7 1365.7,1015.7 1400,1050 1519,1050 1532,1063 ; C17.2@1505,1308.07 1488.07,1325 1378,1325 1365,1312 1365,1083 1385,1063 1419,1063 1532,1063 ; C17.2@1530,1324 1626,1324 1664,1362 1664,1445.91 1702.09,1484 1877.22,1484 1949.22,1412 1949.22,1074.35 1937.87,1063 1532,1063
  Bottom Layer w10: 416,1125 686,1125 1511,1125 1584,1125 1600,1141 1600,1417 1574,1443 144,1443 119,1418 119,1158 152,1125 424,1125
  Bottom Layer w20: v2(537,958) 571,992 682,992 ; 682,1136 682,992 ; v2(860,992) 682,992
  other v1: 1387,1146 1446,1147 1508,1147 1574,1147 1387,1197.67 1446,1198.67 804,1211 861,1211 918,1211 975,1211 145,1219 202,1219 259,1219 316,1219 1573,1247 1387,1249.33 1446,1250.33 1508,1250.57 804,1275 861,1275 918,1275 975,1275 145,1283 202,1283 259,1283 316,1283 1387,1301 1446,1302 1571,1302 804,1337 861,1337 918,1337 975,1337 145,1345 202,1345 259,1345 316,1345 806,1400 863,1400 920,1400 977,1400 147,1408 204,1408 261,1408 318,1408
IS_IN+: R26.2 R27.1 R29.2 U2.48 | length 839.2
  Top Layer w10: U2.48@866.27,358.66 947.34,358.66 1084,222 1264,222 1269,227 R29.2@1269,271.5 ; R29.2@1269,242 1269,224 1300,193 1387,193 1402,208 R26.2@1402,272.5 ; R26.2@1401,261.5 1462.99,323.5 R27.1@1474,323.5
IS_IN-: C16.2 R30.2 R31.1 U2.1 | length 696.2
  Top Layer w10: U2.1@924.34,416.73 928.27,416.73 1073.5,271.5 v2@1095,271.5 ; v2(1095,287) v2@1095,271.5 ; R31.1@1203,271.5 v2@1095,271.5 ; R30.2@1336,271.5 1336,232 v2(1339,229)
  Bottom Layer w10: v2(1095,287) 1332.35,287 1339,280.35 v2(1339,229)
IS_O: C16.1 R31.2 U2.2 | length 344.8
  Top Layer w10: U2.2@924.34,436.42 957.58,436.42 974,420 974,401 1056,319 1187.5,319 R31.2@1203,334.5
LED0: D2.2 U2.28 | length 187
  Top Layer w10: U2.28@591.66,574.21 512.21,574.21 D2.2@451,513 ; D2.2@451,513 D2.2@440.53,513 D2.2@451,513
LED1: D3.2 U2.27 | length 156.1
  Top Layer w10: D3.2@440.53,582 452.43,593.9 499.9,593.9 531.81,593.9 U2.27@591.66,593.9
NetC8_2: C8.2 U1.2 | length 288.3
  Top Layer w8: U1.2@851.49,826.79 870.21,826.79 894,803 896,801
  Top Layer w15: 896,801 915,801 926.03,789.97 C8.2@1124.53,789.97
NetC9_1: C9.1 U1.1 | length 284.7
  Top Layer w8: U1.1@851.49,807.1 851.49,793.51 869,776 899,776
  Top Layer w15: 873,776 896,776 948,724 1042.5,724 C9.1@1053,734.5 ; C9.1@1061.5,722 C9.1@1061.5,732.5
NetC9_2: C9.2 U1.32 | length 284.6
  Top Layer w8: U1.32@825.9,781.51 825.9,761.1 837,750 848,739
  Top Layer w15: 848,739 897,739 964.5,671.5 C9.2@1053,671.5
NetD1_2: D1.2 P2.3 R36.1 | length 229.4
  Top Layer w25: R36.1@458.46,90.5 R36.1@465.46,83.5 ; R36.1@460.21,90.5 646.5,90.5 P2.3@670,114
NetD2_1: D2.1 R2.1 | length 58
  Top Layer w10: R2.1@321.5,515 D2.1@379.47,515
NetD3_1: D3.1 R3.1 | length 58.4
  Top Layer w10: R3.1@322.54,581 R3.1@321.54,582 D3.1@378.47,582
NetP2_2: P2.2 R37.1 | length 87.5
  Top Layer w25: P2.2@777.5,121.5 R37.1@777.5,209
NetQ2_1: Q2.1 R7.2 R32.2 | length 116.3
  Top Layer w25: Q2.1@1206.4,962.24 R32.2@1322.75,962.24
NetQ3_4: Q3.4 U1.5 | length 1241.9
  Top Layer w8: U1.5@851.65,886 931,886 v2(931,888)
  Top Layer w20: v2(901,1045) 931,1075 1090.29,1075 1144,1128.71 1144,1244 1364,1464 1364,1697 1376.04,1709.04 Q3.4@1409,1709.04
  Bottom Layer w20: v2(901,1045) 901,916 931,886 v2(931,888)
NetQ4_4: Q4.4 U1.7 | length 1494.5
  Top Layer w8: U1.7@851.49,925.21 869.76,925.21 892.26,947.71 896.5,947.71
  Top Layer w20: 899,953 925,979 971,979 996,1004 1090,1004 1194,1108 1194,1215.64 1331.36,1353 1605,1353 1630,1378 1630,1505 1649.5,1524.5 1920.5,1524.5 1930,1515 Q4.4@1930,1483.96
NetQ5_1: Q5.1 R34.2 R35.2 | length 122.9
  Top Layer w25: R35.2@1258.6,596.91 Q5.1@1258.6,656.76 ; R34.2@1261.5,530.99 R35.2@1261.5,594
NetQ5_3: Q5.3 R32.1 | length 172.2
  Top Layer w25: Q5.3@1296,751.24 1332,787.24 R32.1@1332,908.5
NetQ6_4: Q6.4 U1.12 | length 1081.4
  Top Layer w8: v2(751,1052) 749,1052 766.87,1034.13 766.87,1001.73 ; U1.12@766.84,970.49 766.84,1001.7
  Top Layer w20: v2(853,1052) 853,1055 906,1108 1075,1108 1100,1133 1100,1151 1100,1685 1122.04,1707.04 Q6.4@1145,1707.04
  Bottom Layer w8: v2@843,1052 v2(853,1052)
  Bottom Layer w20: v2(751,1052) v2@843,1052
NetQ7_1: Q7.1 R39.1 R40.2 | length 334.7
  Top Layer w20: R39.1@914,208.5 991.5,208.5 1028,172 1028,105 1050.4,82.6 1146.09,82.6 R40.2@1154,90.5
NetQ7_3: Q7.3 R37.2 | length 196.3
  Top Layer w25: R37.2@840.5,209 840.5,174.5 850.97,164.03 935.73,164.03 Q7.3@979.76,120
